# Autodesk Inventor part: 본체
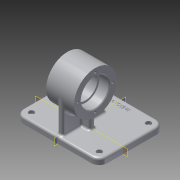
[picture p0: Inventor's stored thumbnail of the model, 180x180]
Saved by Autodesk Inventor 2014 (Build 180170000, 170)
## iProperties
Created: 2019-09
Part Number: 본체
Material: Aluminum 6061
Document SubType Name: Modeling
Designer: kh
Density: 2.71 g/cm^3
Appearance: Aluminum - Flat
Mass: 556.698 g
Surface Area: 495.891 cm^2
Volume: 205.424 cm^3
Author: kh
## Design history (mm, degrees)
sketch "Sketch1"
  geometry: L1 (0, 0)-(126, 0); L2 (126, 0)-(126, 98); L3 (126, 98)-(0, 98); L4 (0, 98)-(0, 0)
  constraints: 8 end point, 2 parallel, 1 horizontal, 1 perpendicular
  dimensions: "d0" = 126 distance of L3.end L2.end; "d1" = 98 distance of L2.end L1.end
extrude "Extrusion1" new body sketch "Sketch1" distance "d2" = 9; taper "d3" = 0 deg
workplane "Work Plane1"
sketch "Sketch2"
  geometry: L1 (126, 9)-(0, 9) reference; L2 (42, 59)-(84, 59); L3 (84, 59)-(84, 91); L4 (84, 91)-(42, 91); L5 (42, 91)-(42, 59); L6 (42, 80)-(57, 80); L7 (57, 80)-(57, 77); L8 (57, 77)-(69, 77); L9 (69, 77)-(69, 80); L10 (69, 80)-(84, 80); L11 (0, 0)-(0, 9) reference; L12 (0, 0)-(126, 0) reference; 1 further point
  constraints: 18 end point, 4 parallel, 4 perpendicular, 2 point on line, 1 horizontal, 1 midpoint
  dimensions: "d5" = 64 diameter of L4 L2; "d6" = 42 distance between parallel lines of L3 L5; "d7" = 36 diameter of L8 L2; "d8" = 42 diameter of L10 L2; "d9" = 42 diameter of L6 L2; "d10" = 15 distance between parallel lines of L7 L5; "d11" = 15 distance between parallel lines of L3 L9; "d14" = 63 distance from line of L11 point (63, 91); "d66" = 59 distance between parallel lines of L12 L2
revolve "Revolution1" sketch "Sketch2" stored, may be unused: angle "d15" = 90 deg
sketch "Sketch3"
  geometry: L1 (46, 32)-(80, 32); L2 (80, 32)-(80, 40); L3 (80, 40)-(46, 40); L4 (46, 40)-(46, 32); L5 (46, 32)-(80, 40); L6 (80, 32)-(46, 40); L7 (0, 98)-(0, 0) reference; L8 (126, 98)-(0, 98) reference; 1 further point
  constraints: 12 end point, 2 midpoint, 2 parallel, 1 horizontal, 1 perpendicular
  dimensions: "d16" = 63 distance from line of point (63, 36) L7; "d17" = 8 distance between parallel lines of L1 L3; "d18" = 34 distance between parallel lines of L2 L4; "d19" = 62 distance from line of L8 point (63, 36)
extrude "Extrusion2" join sketch "Sketch3" stored distance "d20" = 0; taper "d21" = 0 deg
workplane "Work Plane2"
sketch "Sketch4"
  geometry: L1 (59, 68)-(-0.046, 68); L2 (59, 4)-(-0.046, 4); A1 r 32 centre (59, 36) between (59, 68) and (59, 4) reference; 1 further point
  constraints: 4 end point, 2 point on circle, 2 tangent, 1 horizontal, 1 parallel
feature "Rib1" sketch "Sketch4" dims "d23" = 1, "d24" = 8, "d25" = 0, "d26" = 0, "d27" = 1, "d28" = 1
mirror "Mirror1"
sketch "Sketch5"
  geometry: L1 (0, 0)-(26, 0); C1 r 32 at (0, 0) reference; 2 further points
  constraints: 2 end point, 1 coincident, 1 horizontal
  dimensions: "d29" = 26 distance of L1.start point (26, 0)
hole "Hole1" sketch "Sketch5" at (26, 0) diameter "d30" = 3.242; stored, may be unused: countersink angle "d34" = 90 deg, drill point angle "d36" = 118 deg; dims "d31" = 8, "d32" = 4, "d33" = 2, "d35" = 10
pattern_circular "Circular Pattern1" dims angle "d38" = 360 deg
mirror "Mirror2"
fillet "Fillet1" dims "d40" = 3
fillet "Fillet3" dims "d42" = 12
fillet "Fillet2" dims "d41" = 3
hole "Hole2" diameter "d45" = 4.5; stored, may be unused: countersink angle "d49" = 90 deg, drill point angle "d51" = 118 deg; dims "d43" = 10, "d44" = 10, "d46" = 8, "d47" = 8, "d48" = 4.4, "d50" = 10
pattern_linear "Rectangular Pattern1" dims "d54" = 74, "d57" = 102
fillet "Fillet4" dims "d58" = 0.3
sketch "Sketch6"
  geometry: L1 (49.482, 92.439)-(76.518, 92.439); L2 (76.518, 92.439)-(76.518, 83.561); L3 (76.518, 83.561)-(49.482, 83.561); L4 (49.482, 83.561)-(49.482, 92.439); L5 (49.482, 92.439)-(76.518, 83.561); L6 (76.518, 92.439)-(49.482, 83.561); L7 (114, 98)-(12, 98) reference; L8 (126, 12)-(126, 86) reference; 2 further points
  constraints: 4 end point, 1 midpoint, 2 other
  dimensions: "d59" = 10 distance from line of point (63, 88) L7; "d60" = 63 distance from line of L8 point (63, 88)
emboss "Emboss1" sketch "Sketch6" dims "d0" = 126, "d1" = 98, "d61" = 0.5, "d62" = 0
chamfer "Chamfer1" distance "d63" = 1; stored, may be unused: second distance "d64" = 2, angle "d65" = 45 deg
body "Solid1"
other parameters: "d4" = -36, "d22" = -63
